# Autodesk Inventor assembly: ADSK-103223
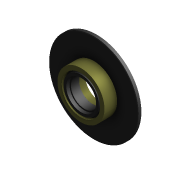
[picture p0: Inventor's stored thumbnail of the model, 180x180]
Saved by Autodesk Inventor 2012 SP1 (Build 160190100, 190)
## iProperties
Shininess: 0.0
Created: 2000-11
Part Number: ADSK-103223
Document SubType Name: Assembly
Stock Number: ADSK-103223
Density: 0.0
Volumn: 0.0
Area: 0.0
PropertySet Name: Model Information
Control State: 0
Master: False
Checked Out: False
Author: gao
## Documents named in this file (4)
- D:\AOTC\Autodesk Inventor 2012 Essential for New Users\Autodesk Inventor 2012 Essentials - Project Files\Learning\Workspace\Sub-Assemblies\ADSK-103223.iam
- D:\AOTC\Autodesk Inventor 2012 Essential for New Users\Autodesk Inventor 2012 Essentials - Project Files\Learning\Workspace\Parts\ADSK-103867.ipt
- D:\AOTC\Autodesk Inventor 2012 Essential for New Users\Autodesk Inventor 2012 Essentials - Project Files\Learning\Workspace\Parts\ADSK-103991.ipt
- D:\AOTC\Autodesk Inventor 2012 Essential for New Users\Autodesk Inventor 2012 Essentials - Project Files\Learning\Workspace\Parts\ADSK-103989.ipt
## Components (3 placed, 3 different names)
1. ADSK-103991:1 — Insert:1, Insert:2
2. ADSK-103867:1 — Insert:1
3. ADSK-103989:1 — Insert:2
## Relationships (2: Insert 2)
- Insert:1: ADSK-103991:1 ↔ ADSK-103867:1
- Insert:2: ADSK-103991:1 ↔ ADSK-103989:1
